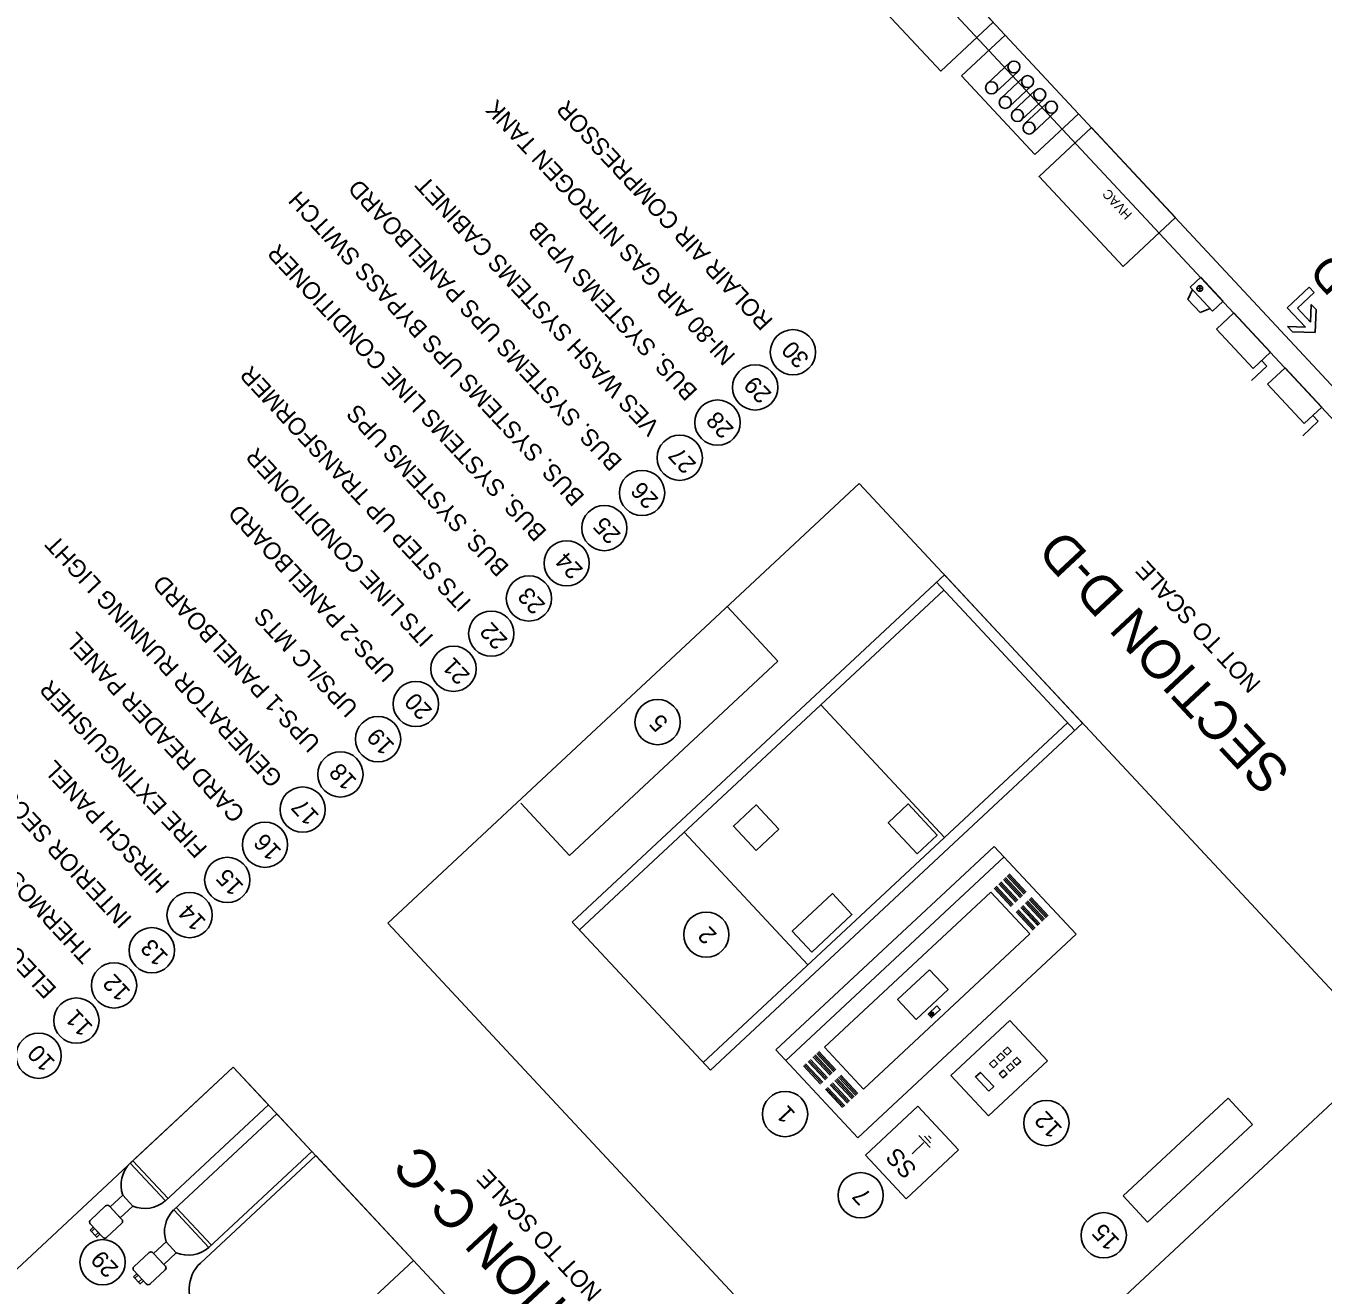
# Model space of a CAD drawing. Extents: x 1121979 to 1130574, y 1838676 to 1848573.
# Drawn here: x 1129626.56 to 1129644.68, y 1839379.61 to 1839397.19 of the extents above; entities that cross this region are included whole.
import ezdxf

# ---------------------------------------------------------------- set-up
doc = ezdxf.new("R2010")
doc.units = 0
for name, color, linetype in [('Future by Others', 7, 'Continuous'), ('GE-NOT-Notes', 7, 'Continuous'), ('HS_Dimensions and Text', 7, 'Continuous'), ('IPDC BUILDING RELATED', 7, 'Continuous'), ('IPDC ELEC POWER CABINETS', 7, 'Continuous'), ('IPDC-EXIST ELECT EQUIP', 7, 'Continuous'), ('IT-PCM-Proposed Communications Conduit', 7, 'Continuous'), ('Level 4', 7, 'Continuous'), ('Sheet Text', 7, 'Continuous'), ('Sheets_General Details', 7, 'Continuous')]:
    doc.layers.add(name, color=color, linetype=linetype)

msp = doc.modelspace()

# ---------------------------------------------------------------- linework, layer by layer
at = {"layer": 'Future by Others'}
for p, q in [((1129642.994, 1839393.524), (1129642.915, 1839393.526)), ((1129642.956, 1839393.565), (1129642.953, 1839393.486))]:
    msp.add_line(p, q, dxfattribs=at)
msp.add_circle((1129642.954, 1839393.525), 0.0396, dxfattribs=at)
at = {"layer": 'GE-NOT-Notes'}
for p, q in [((1129644.483, 1839393.542), (1129644.176, 1839393.255)), ((1129644.551, 1839393.468), (1129644.483, 1839393.542)), ((1129644.551, 1839393.468), (1129644.317, 1839393.25)), ((1129644.176, 1839393.255), (1129644.428, 1839392.985)), ((1129644.317, 1839393.25), (1129644.501, 1839393.053)), ((1129644.501, 1839393.053), (1129644.51, 1839393.302)), ((1129644.578, 1839393.229), (1129644.51, 1839393.302)), ((1129644.567, 1839392.909), (1129644.578, 1839393.229)), ((1129644.428, 1839392.985), (1129644.179, 1839392.994)), ((1129644.248, 1839392.92), (1129644.179, 1839392.994)), ((1129644.567, 1839392.909), (1129644.248, 1839392.92))]:
    msp.add_line(p, q, dxfattribs=at)
at = {"layer": 'IPDC BUILDING RELATED'}
for p, q in [((1129631.615, 1839384.664), (1129638.197, 1839390.802)), ((1129638.197, 1839390.802), (1129645.58, 1839382.884)), ((1129631.615, 1839384.664), (1129638.997, 1839376.747)), ((1129638.997, 1839376.747), (1129645.58, 1839382.884)), ((1129629.458, 1839382.653), (1129622.876, 1839376.516)), ((1129636.841, 1839374.736), (1129629.458, 1839382.653))]:
    msp.add_line(p, q, dxfattribs=at)
for points in [[(1129635.108, 1839402.107), (1129648.066, 1839388.211), (1129652.454, 1839392.303), (1129652.117, 1839392.664)], [(1129652.084, 1839392.292), (1129648.126, 1839388.601), (1129635.548, 1839402.09)]]:
    msp.add_lwpolyline(points, dxfattribs=at)
for points in [[(1129638.899, 1839398.497), (1129638.167, 1839397.815), (1129639.34, 1839396.558), (1129640.071, 1839397.24)], [(1129641.441, 1839395.77), (1129640.71, 1839395.088), (1129641.882, 1839393.831), (1129642.613, 1839394.513)]]:
    msp.add_lwpolyline(points, close=True, dxfattribs=at)
at = {"layer": 'IPDC ELEC POWER CABINETS'}
for p, q in [((1129642.821, 1839393.543), (1129642.967, 1839393.68)), ((1129643.132, 1839393.209), (1129642.821, 1839393.543)), ((1129643.279, 1839393.345), (1129642.967, 1839393.68)), ((1129642.787, 1839393.37), (1129642.852, 1839393.51)), ((1129642.957, 1839393.187), (1129642.787, 1839393.37)), ((1129643.132, 1839393.209), (1129643.279, 1839393.345)), ((1129642.957, 1839393.187), (1129643.101, 1839393.243)), ((1129643.429, 1839393.184), (1129643.185, 1839392.957)), ((1129643.429, 1839393.184), (1129643.941, 1839392.636)), ((1129643.185, 1839392.957), (1129643.697, 1839392.408)), ((1129643.941, 1839392.636), (1129643.697, 1839392.408)), ((1129643.892, 1839392.439), (1129643.675, 1839392.237)), ((1129643.816, 1839392.52), (1129643.892, 1839392.439)), ((1129644.145, 1839392.416), (1129643.901, 1839392.189)), ((1129644.145, 1839392.416), (1129644.657, 1839391.868)), ((1129643.901, 1839392.189), (1129644.413, 1839391.64)), ((1129644.657, 1839391.868), (1129644.413, 1839391.64)), ((1129644.533, 1839391.752), (1129644.608, 1839391.671)), ((1129644.608, 1839391.671), (1129644.391, 1839391.469))]:
    msp.add_line(p, q, dxfattribs=at)
at = {"layer": 'IPDC-EXIST ELECT EQUIP'}
for p, q in [((1129640.238, 1839397.061), (1129639.628, 1839396.492)), ((1129640.651, 1839395.395), (1129639.628, 1839396.492)), ((1129641.26, 1839395.963), (1129640.651, 1839395.395)), ((1129634.191, 1839384.679), (1129639.388, 1839389.525)), ((1129641.209, 1839387.352), (1129639.278, 1839389.422)), ((1129641.318, 1839387.455), (1129639.388, 1839389.525)), ((1129634.293, 1839384.569), (1129639.381, 1839389.313)), ((1129637.064, 1839388.321), (1129636.354, 1839389.083)), ((1129634.154, 1839385.607), (1129637.064, 1839388.321)), ((1129639.388, 1839385.859), (1129637.662, 1839387.71)), ((1129636.019, 1839382.718), (1129641.106, 1839387.462)), ((1129636.121, 1839382.609), (1129641.318, 1839387.455)), ((1129634.154, 1839385.607), (1129633.472, 1839386.339)), ((1129637.482, 1839384.082), (1129635.756, 1839385.933)), ((1129640.083, 1839385.735), (1129637.035, 1839382.894)), ((1129640.221, 1839385.587), (1129637.173, 1839382.746)), ((1129637.939, 1839383.459), (1129640.221, 1839385.587)), ((1129641.226, 1839384.509), (1129640.083, 1839385.735)), ((1129640.385, 1839384.958), (1129640.147, 1839385.213)), ((1129640.4, 1839384.971), (1129640.161, 1839385.227)), ((1129640.414, 1839384.985), (1129640.176, 1839385.241)), ((1129640.451, 1839385.019), (1129640.212, 1839385.275)), ((1129640.466, 1839385.033), (1129640.227, 1839385.289)), ((1129640.48, 1839385.046), (1129640.242, 1839385.302)), ((1129640.502, 1839385.067), (1129640.264, 1839385.323)), ((1129640.517, 1839385.08), (1129640.278, 1839385.336)), ((1129640.531, 1839385.094), (1129640.293, 1839385.35)), ((1129640.036, 1839385.098), (1129637.715, 1839382.933)), ((1129640.036, 1839385.098), (1129640.581, 1839384.513)), ((1129640.319, 1839384.896), (1129640.081, 1839385.152)), ((1129640.334, 1839384.91), (1129640.095, 1839385.166)), ((1129640.349, 1839384.923), (1129640.11, 1839385.179)), ((1129640.838, 1839384.765), (1129640.6, 1839385.021)), ((1129640.641, 1839384.581), (1129640.402, 1839384.837)), ((1129640.655, 1839384.594), (1129640.417, 1839384.85)), ((1129640.692, 1839384.629), (1129640.453, 1839384.884)), ((1129640.707, 1839384.642), (1129640.468, 1839384.898)), ((1129640.721, 1839384.656), (1129640.483, 1839384.912)), ((1129640.758, 1839384.69), (1129640.519, 1839384.946)), ((1129640.772, 1839384.704), (1129640.534, 1839384.959)), ((1129640.787, 1839384.717), (1129640.548, 1839384.973)), ((1129640.809, 1839384.738), (1129640.57, 1839384.994)), ((1129640.824, 1839384.751), (1129640.585, 1839385.007)), ((1129636.121, 1839382.609), (1129634.191, 1839384.679)), ((1129640.626, 1839384.567), (1129640.388, 1839384.823)), ((1129641.226, 1839384.509), (1129638.181, 1839381.665)), ((1129640.581, 1839384.513), (1129638.26, 1839382.348)), ((1129639.193, 1839383.386), (1129639.228, 1839383.419)), ((1129639.236, 1839383.41), (1129639.201, 1839383.377)), ((1129639.478, 1839382.537), (1129640.301, 1839383.304)), ((1129640.827, 1839382.74), (1129640.301, 1839383.304)), ((1129638.181, 1839381.665), (1129637.035, 1839382.894)), ((1129637.843, 1839382.587), (1129637.605, 1839382.843)), ((1129637.858, 1839382.601), (1129637.619, 1839382.857)), ((1129637.872, 1839382.615), (1129637.634, 1839382.87)), ((1129638.26, 1839382.348), (1129637.715, 1839382.933)), ((1129637.66, 1839382.417), (1129637.422, 1839382.673)), ((1129637.675, 1839382.43), (1129637.436, 1839382.686)), ((1129637.69, 1839382.444), (1129637.451, 1839382.7)), ((1129637.726, 1839382.478), (1129637.488, 1839382.734)), ((1129637.741, 1839382.492), (1129637.502, 1839382.748)), ((1129637.755, 1839382.505), (1129637.517, 1839382.761)), ((1129637.792, 1839382.54), (1129637.553, 1839382.795)), ((1129637.807, 1839382.553), (1129637.568, 1839382.809)), ((1129637.821, 1839382.567), (1129637.583, 1839382.823)), ((1129640.004, 1839381.973), (1129640.827, 1839382.74)), ((1129629.458, 1839382.653), (1129628.02, 1839381.312)), ((1129629.458, 1839382.653), (1129629.95, 1839382.126)), ((1129638.113, 1839382.224), (1129637.875, 1839382.48)), ((1129638.128, 1839382.238), (1129637.889, 1839382.494)), ((1129638.15, 1839382.258), (1129637.911, 1839382.514)), ((1129638.165, 1839382.272), (1129637.926, 1839382.528)), ((1129638.179, 1839382.286), (1129637.941, 1839382.541)), ((1129640.004, 1839381.973), (1129639.478, 1839382.537)), ((1129637.967, 1839382.088), (1129637.728, 1839382.344)), ((1129637.982, 1839382.101), (1129637.743, 1839382.357)), ((1129637.996, 1839382.115), (1129637.758, 1839382.371)), ((1129638.033, 1839382.149), (1129637.794, 1839382.405)), ((1129638.048, 1839382.163), (1129637.809, 1839382.419)), ((1129638.062, 1839382.176), (1129637.824, 1839382.432)), ((1129638.099, 1839382.211), (1129637.86, 1839382.466)), ((1129629.95, 1839382.126), (1129628.511, 1839380.785)), ((1129641.885, 1839380.855), (1129643.348, 1839382.219)), ((1129643.348, 1839382.219), (1129643.689, 1839381.853)), ((1129630.065, 1839382.002), (1129628.627, 1839380.661)), ((1129630.065, 1839382.002), (1129630.557, 1839381.475)), ((1129638.286, 1839381.425), (1129639.017, 1839382.107)), ((1129639.585, 1839381.498), (1129639.017, 1839382.107)), ((1129642.226, 1839380.489), (1129643.689, 1839381.853)), ((1129638.937, 1839381.445), (1129639.103, 1839381.6)), ((1129639.188, 1839381.531), (1129639.033, 1839381.697)), ((1129639.194, 1839381.598), (1129639.108, 1839381.69)), ((1129639.204, 1839381.656), (1129639.166, 1839381.696)), ((1129630.61, 1839381.418), (1129629.001, 1839379.917)), ((1129630.557, 1839381.475), (1129629.118, 1839380.134)), ((1129630.61, 1839381.418), (1129631.974, 1839379.955)), ((1129638.854, 1839380.816), (1129638.286, 1839381.425)), ((1129638.854, 1839380.816), (1129639.585, 1839381.498)), ((1129628.02, 1839381.312), (1129628.511, 1839380.785)), ((1129628.057, 1839381.347), (1129628.549, 1839380.82)), ((1129642.226, 1839380.489), (1129641.885, 1839380.855)), ((1129627.464, 1839380.517), (1129627.677, 1839380.716)), ((1129627.73, 1839380.714), (1129627.904, 1839380.527)), ((1129628.664, 1839380.696), (1129629.156, 1839380.169)), ((1129628.627, 1839380.661), (1129629.118, 1839380.134)), ((1129627.462, 1839380.464), (1129627.636, 1839380.278)), ((1129627.478, 1839380.357), (1129627.523, 1839380.399)), ((1129627.531, 1839380.301), (1129627.575, 1839380.343)), ((1129627.689, 1839380.276), (1129627.902, 1839380.474)), ((1129628.071, 1839379.866), (1129628.284, 1839380.065)), ((1129628.337, 1839380.063), (1129628.511, 1839379.876)), ((1129631.974, 1839379.955), (1129630.365, 1839378.455)), ((1129628.069, 1839379.813), (1129628.243, 1839379.627)), ((1129628.296, 1839379.625), (1129628.509, 1839379.823)), ((1129628.085, 1839379.706), (1129628.13, 1839379.748)), ((1129628.138, 1839379.65), (1129628.182, 1839379.692))]:
    msp.add_line(p, q, dxfattribs=at)
for points in [[(1129636.759, 1839385.679), (1129636.443, 1839386.019), (1129636.759, 1839386.313), (1129637.075, 1839385.974)], [(1129639.006, 1839385.632), (1129638.603, 1839386.065), (1129638.884, 1839386.327), (1129639.287, 1839385.894)], [(1129637.535, 1839384.26), (1129637.263, 1839384.553), (1129637.824, 1839385.077), (1129638.097, 1839384.784)], [(1129639.18, 1839384.013), (1129639.439, 1839383.735), (1129638.994, 1839383.32), (1129638.735, 1839383.598)], [(1129639.284, 1839383.508), (1129639.329, 1839383.459), (1129639.208, 1839383.346), (1129639.162, 1839383.395)], [(1129640.173, 1839382.738), (1129640.12, 1839382.794), (1129640.178, 1839382.848), (1129640.23, 1839382.792)], [(1129640.263, 1839382.822), (1129640.21, 1839382.878), (1129640.268, 1839382.932), (1129640.321, 1839382.876)], [(1129640.073, 1839382.644), (1129640.02, 1839382.701), (1129640.078, 1839382.755), (1129640.13, 1839382.698)], [(1129640.253, 1839382.652), (1129640.305, 1839382.596), (1129640.363, 1839382.649), (1129640.31, 1839382.706)], [(1129640.343, 1839382.736), (1129640.395, 1839382.68), (1129640.453, 1839382.733), (1129640.401, 1839382.79)], [(1129640.007, 1839382.317), (1129639.822, 1839382.516), (1129639.891, 1839382.58), (1129640.076, 1839382.381)], [(1129640.153, 1839382.559), (1129640.205, 1839382.502), (1129640.263, 1839382.556), (1129640.211, 1839382.612)], [(1129627.74, 1839380.703), (1129627.882, 1839380.551), (1129628.057, 1839380.714), (1129627.915, 1839380.866)], [(1129627.46, 1839380.378), (1129627.552, 1839380.278), (1129627.597, 1839380.32), (1129627.504, 1839380.419)], [(1129628.347, 1839380.052), (1129628.489, 1839379.9), (1129628.664, 1839380.063), (1129628.522, 1839380.215)], [(1129628.066, 1839379.727), (1129628.159, 1839379.627), (1129628.204, 1839379.669), (1129628.111, 1839379.768)]]:
    msp.add_lwpolyline(points, close=True, dxfattribs=at)
msp.add_circle((1129639.214, 1839383.398), 0.025, dxfattribs=at)
for centre, radius, start, end in [((1129628.326, 1839381.005), 0.434, 134.9201, 198.6864), ((1129627.703, 1839380.688), 0.0376, 42.9971, 132.9971), ((1129628.224, 1839381.114), 0.434, 247.3079, 311.0742), ((1129627.49, 1839380.49), 0.0376, 132.9971, 222.9971), ((1129627.877, 1839380.502), 0.0376, 312.9971, 42.9971), ((1129628.933, 1839380.354), 0.434, 134.9201, 198.6864), ((1129627.664, 1839380.303), 0.0376, 222.9971, 312.9971), ((1129628.831, 1839380.463), 0.434, 247.3079, 311.0742), ((1129628.31, 1839380.037), 0.0376, 42.9971, 132.9971), ((1129628.097, 1839379.839), 0.0376, 132.9971, 222.9971), ((1129628.483, 1839379.851), 0.0376, 312.9971, 42.9971), ((1129629.342, 1839379.552), 0.5, 132.9971, 222.9971), ((1129628.271, 1839379.652), 0.0376, 222.9971, 312.9971)]:
    msp.add_arc(centre, radius, start, end, dxfattribs=at)
at = {"layer": 'IT-PCM-Proposed Communications Conduit'}
for p, q in [((1129640.302, 1839396.678), (1129639.989, 1839396.386)), ((1129640.416, 1839396.555), (1129640.104, 1839396.264)), ((1129640.492, 1839396.473), (1129640.18, 1839396.182)), ((1129640.606, 1839396.351), (1129640.294, 1839396.06)), ((1129640.662, 1839396.291), (1129640.35, 1839396)), ((1129640.776, 1839396.169), (1129640.464, 1839395.878)), ((1129640.825, 1839396.116), (1129640.513, 1839395.825)), ((1129640.939, 1839395.994), (1129640.627, 1839395.703))]:
    msp.add_line(p, q, dxfattribs=at)
for centre in [(1129640.359, 1839396.616), (1129640.549, 1839396.412), (1129640.046, 1839396.325), (1129640.719, 1839396.23), (1129640.237, 1839396.121), (1129640.882, 1839396.055), (1129640.407, 1839395.939), (1129640.57, 1839395.764)]:
    msp.add_circle(centre, 0.0836, dxfattribs=at)
at = {"layer": 'Level 4'}
for centre in [(1129637.273, 1839392.634), (1129636.746, 1839392.143), (1129636.22, 1839391.651), (1129635.693, 1839391.16), (1129635.167, 1839390.669), (1129634.64, 1839390.178), (1129634.114, 1839389.687), (1129633.587, 1839389.196), (1129633.061, 1839388.705), (1129632.534, 1839388.214), (1129632.008, 1839387.723), (1129635.384, 1839387.47), (1129631.481, 1839387.232), (1129630.955, 1839386.74), (1129630.428, 1839386.249), (1129629.902, 1839385.758), (1129629.375, 1839385.267), (1129628.849, 1839384.776), (1129636.064, 1839384.503), (1129628.322, 1839384.285), (1129627.795, 1839383.794), (1129627.269, 1839383.303), (1129626.742, 1839382.812), (1129637.163, 1839381.998), (1129640.813, 1839381.872), (1129638.219, 1839380.865), (1129641.613, 1839380.306), (1129627.634, 1839379.93)]:
    msp.add_circle(centre, 0.316, dxfattribs=at)
at = {"layer": 'Sheets_General Details'}
for p, q in [((1129644.483, 1839393.542), (1129644.176, 1839393.255)), ((1129644.551, 1839393.468), (1129644.483, 1839393.542)), ((1129644.317, 1839393.25), (1129644.551, 1839393.468)), ((1129644.176, 1839393.255), (1129644.428, 1839392.985)), ((1129644.501, 1839393.053), (1129644.317, 1839393.25)), ((1129644.51, 1839393.302), (1129644.501, 1839393.053)), ((1129644.578, 1839393.229), (1129644.51, 1839393.302)), ((1129644.567, 1839392.909), (1129644.578, 1839393.229)), ((1129644.428, 1839392.985), (1129644.179, 1839392.994)), ((1129644.179, 1839392.994), (1129644.248, 1839392.92)), ((1129644.248, 1839392.92), (1129644.567, 1839392.909))]:
    msp.add_line(p, q, dxfattribs=at)

# ---------------------------------------------------------------- texts
at = {"layer": 'GE-NOT-Notes'}
msp.add_text('D', height=0.48, rotation=132.9971, dxfattribs=at).set_placement((1129645.118, 1839393.72))
at = {"layer": 'HS_Dimensions and Text'}
for s, height, p in [('HVAC', 0.1333, (1129642.018, 1839394.563)), ('NOT TO SCALE', 0.24, (1129643.82, 1839388.018)), ('NOT TO SCALE', 0.24, (1129634.621, 1839379.524))]:
    msp.add_text(s, height=height, rotation=132.9971, dxfattribs=at).set_placement(p)
at = {"layer": 'IPDC-EXIST ELECT EQUIP'}
msp.add_text('SS', height=0.24, rotation=132.9971, dxfattribs=at).set_placement((1129639.017, 1839381.235))
at = {"layer": 'Level 4'}
for s, p in [('30', (1129637.514, 1839392.551)), ('29', (1129636.988, 1839392.059)), ('28', (1129636.461, 1839391.568)), ('27', (1129635.935, 1839391.077)), ('26', (1129635.408, 1839390.586)), ('25', (1129634.882, 1839390.095)), ('24', (1129634.355, 1839389.604)), ('23', (1129633.829, 1839389.113)), ('22', (1129633.302, 1839388.622)), ('21', (1129632.776, 1839388.131)), ('20', (1129632.249, 1839387.64)), ('5', (1129635.545, 1839387.473)), ('19', (1129631.723, 1839387.148)), ('18', (1129631.196, 1839386.657)), ('17', (1129630.67, 1839386.166)), ('16', (1129630.143, 1839385.675)), ('15', (1129629.617, 1839385.184)), ('14', (1129629.09, 1839384.693)), ('2', (1129636.224, 1839384.507)), ('13', (1129628.564, 1839384.202)), ('12', (1129628.037, 1839383.711)), ('11', (1129627.511, 1839383.22)), ('10', (1129626.984, 1839382.729)), ('1', (1129637.32, 1839382.006)), ('12', (1129641.046, 1839381.798)), ('7', (1129638.381, 1839380.868)), ('15', (1129641.847, 1839380.231)), ('29', (1129627.87, 1839379.853))]:
    msp.add_text(s, height=0.24, rotation=132.9971, dxfattribs=at).set_placement(p)
at = {"layer": 'Sheet Text'}
for s, p in [('NI-80 AIR GAS NITROGEN TANK', (1129636.483, 1839392.59)), ('ROLAIR AIR COMPRESSOR', (1129637.009, 1839393.081)), ('BUS. SYSTEMS UPS PANELBOARD', (1129634.903, 1839391.117)), ('VES WASH SYSTEMS CABINET', (1129635.43, 1839391.608)), ('BUS. SYSTEMS UPS BYPASS SWITCH', (1129634.377, 1839390.626)), ('BUS. SYSTEMS VPJB', (1129635.956, 1839392.099)), ('BUS. SYSTEMS LINE CONDITIONER', (1129633.85, 1839390.134)), ('ITS STEP UP TRANSFORMER', (1129632.797, 1839389.152)), ('BUS. SYSTEMS UPS', (1129633.323, 1839389.643)), ('ITS LINE CONDITIONER', (1129632.27, 1839388.661)), ('UPS-2 PANELBOARD ', (1129631.744, 1839388.17)), ('GENERATOR RUNNING LIGHT', (1129630.164, 1839386.697)), ('UPS-1 PANELBOARD', (1129630.691, 1839387.188)), ('INTERIOR SECURITY CAMERA CCTV 1', (1129628.058, 1839384.732)), ('UPS/LC MTS', (1129631.217, 1839387.679)), ('CARD READER PANEL', (1129629.638, 1839386.206)), ('FIRE EXTINGUISHER', (1129629.111, 1839385.714)), ('HIRSCH PANEL ', (1129628.585, 1839385.223)), ('ELECTRIC HEATER', (1129627.005, 1839383.75)), ('THERMOSTAT', (1129627.532, 1839384.241))]:
    msp.add_text(s, height=0.24, rotation=133.0067, dxfattribs=at).set_placement(p)
at = {"layer": 'Sheets_General Details'}
for s, p in [('SECTION D-D', (1129644.242, 1839386.779)), ('SECTION C-C', (1129635.237, 1839378.183))]:
    msp.add_text(s, height=0.53756, rotation=132.9971, dxfattribs=at).set_placement(p)

doc.saveas('drawing.dxf')
